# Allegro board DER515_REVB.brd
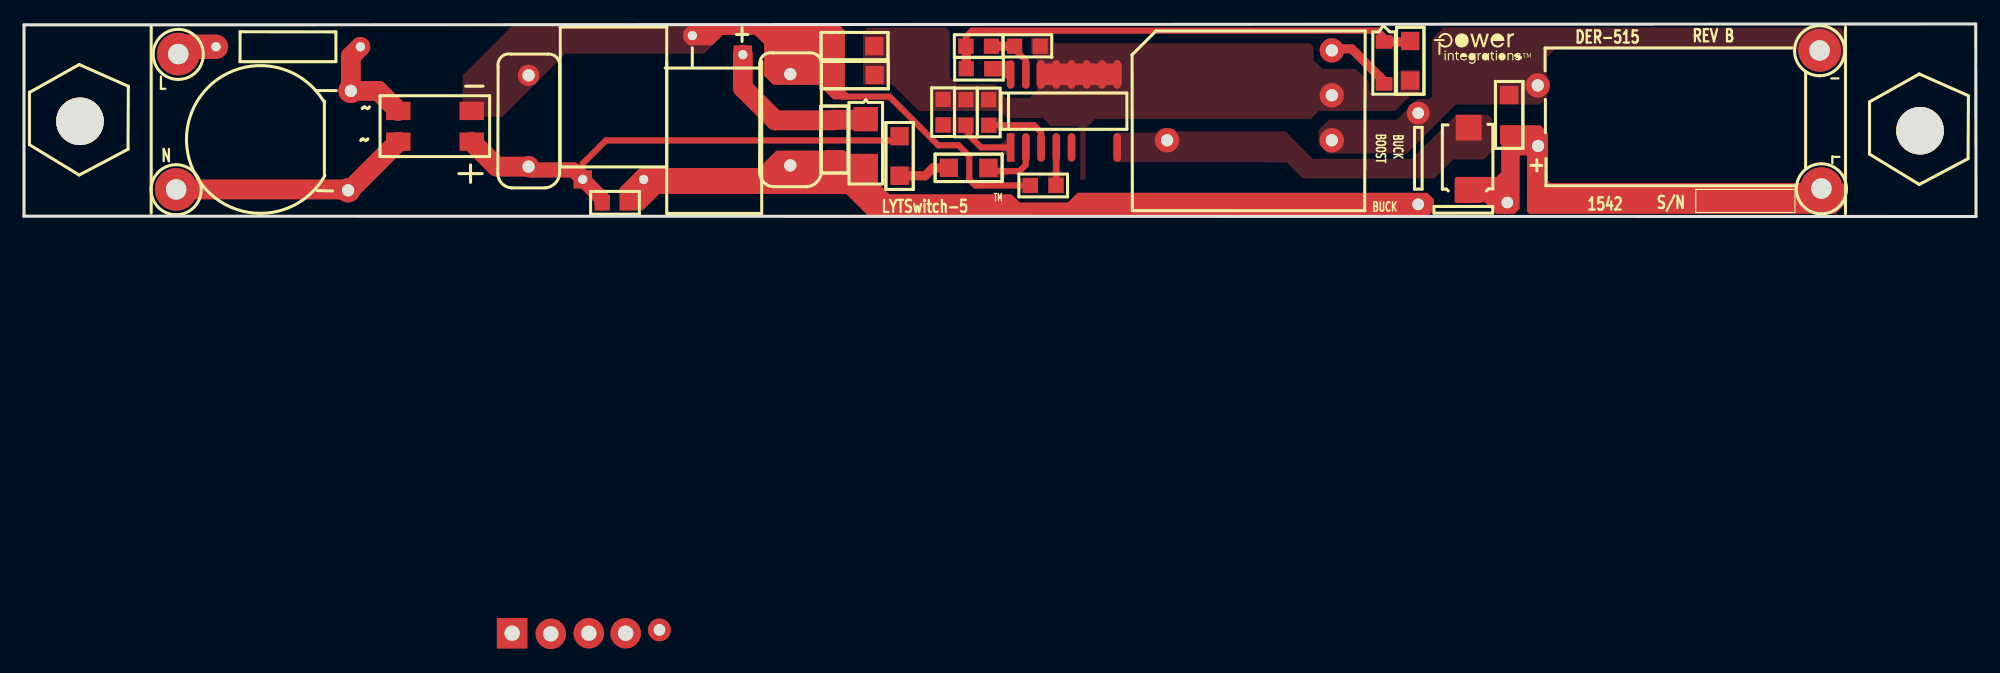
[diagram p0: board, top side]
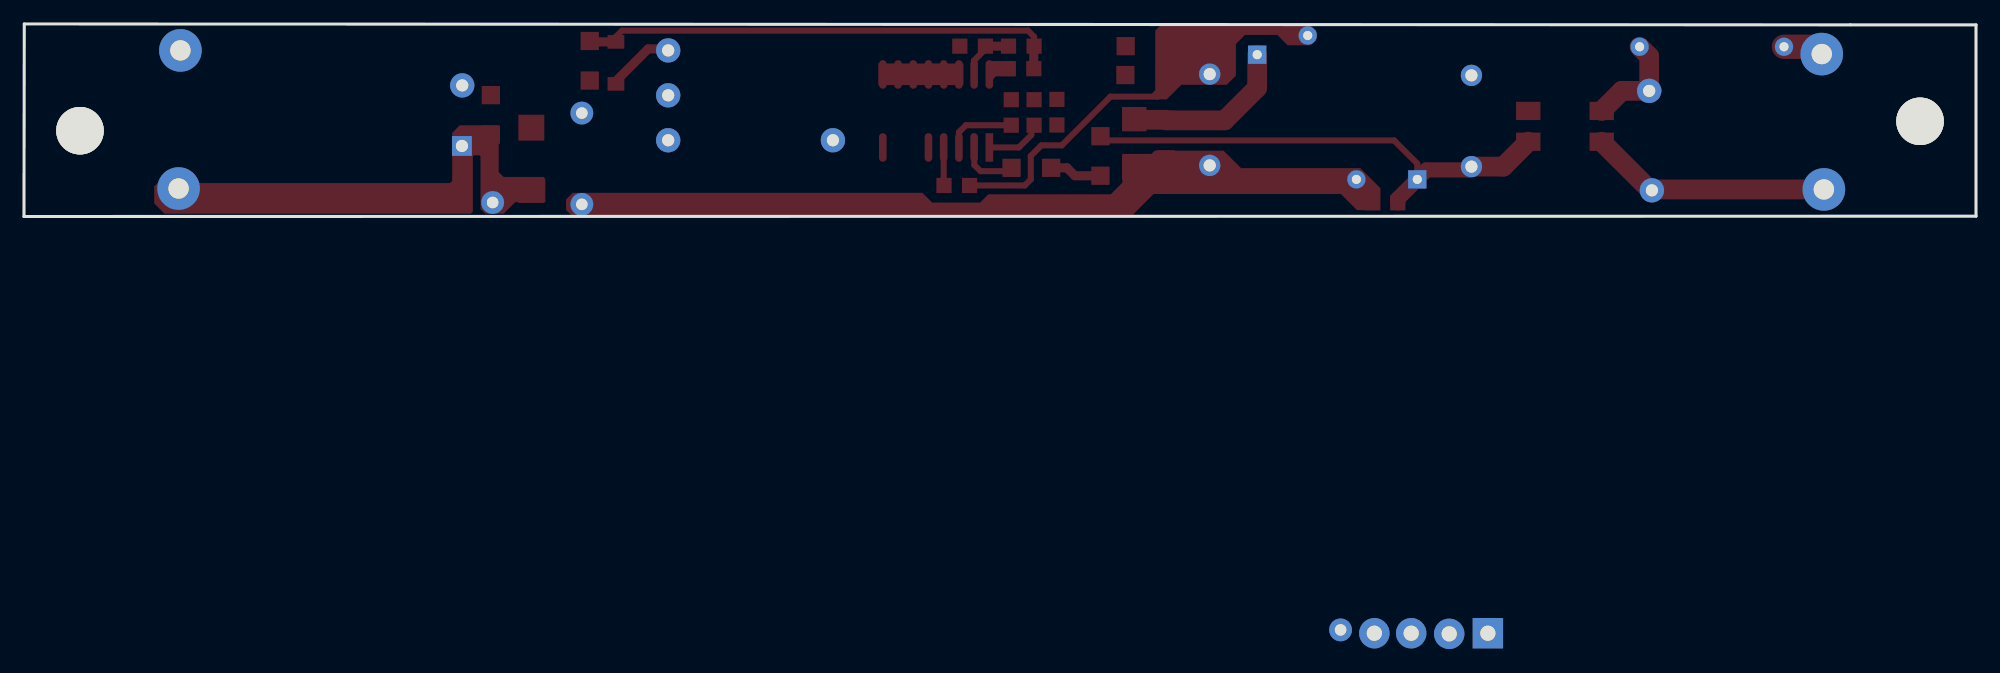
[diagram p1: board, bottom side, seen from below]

Outline 162.92 x 16.08 mm; copper layers: TOP, BOTTOM. Coordinates in mm from the lower left corner of the outline.
Outline path: 0,16 10.49,16 162.89,16.08 162.92,0 0,0.03 0,16

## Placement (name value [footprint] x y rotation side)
BR1  B10S-G  [PISMSOIC4]  31.24 8.81 270 top
C1  100 nF  [PINPCAPRAD440X200300040]  42.11 4.17 90 top
C2  100 nF  [PINPCAPRAD440X200300040]  63.96 4.27 90 top
C3  2.2 uF  [PIPOLCAPCLYD320LS140030]  57.61 15.37 180 top
C4  10uF  [PISMC1206]  67.69 11.81 0 top
C5  1 uF  [PISMC0805]  82.68 14.22 0 top
C6  150 nF  [PISMC0805]  78.61 7.62 90 top
C7  10uF  [PISMC1206]  115.7 14.66 270 top
C8  100 uF  [PIPOLCAPCYLD400LS200040]  126.42 11 270 bottom
D5  RS1K  [PISMDSMA]  70.26 8.13 270 top
D6  BAV21W-7-F  [PI_SM_SOD-123_12]  113.51 14.58 270 top
D7  MURS160T3G  [PISMSMB]  120.57 2.21 90 top
F1  5 A  [PI_V_AXIAL_160LS150D030]  22.38 14.17 180 top
JP1  J  [PI_JUMPER300]  116.36 8.64 270 top
JP2  J  [PI_JUMPER300#2]  116.18 1.17 0 top
L1  3.3 mH  [PI_CHOKE_450HX375LS197D030_H]  46.69 1.88 0 top
NOREF  -  []  0.03 0.05 0 top
NOREF#2  -  []  162.92 0 90 top
NOREF#3  -  []  117.12 15.21 0 top
NOREF#4  -  []  -158.2 54.23 0 top
NOREF#5  -  []  -236.02 -144.78 0 top
POST-CRKT_BRD_6-32_HEX1  Post Hex, 6-32, snap, 0.375L, NYL  [PIMTGHOLED156]  4.67 7.95 90 top
POST-CRKT_BRD_6-32_HEX2  Post Hex, 6-32, snap, 0.375L, NYL  [PIMTGHOLED156]  158.24 7.16 90 top
R1  10 k  [PISMR0805]  48.26 1.14 0 top
R2  680 k  [PISMR1206]  67.64 4.78 90 top
R3  2.00 M  [PISMR1206]  73.08 6.71 270 top
R4  2.00 M  [PISMR1206]  77.19 4.06 0 top
R5  100 k  [PISMR0805]  80.77 12.34 180 top
R6  6.2 k  [PISMR0805]  78.61 14.22 0 top
R7  6.04 k  [PISMR0805]  80.52 7.62 90 top
R8  6.04 k  [PISMR0805]  86.13 2.59 180 top
R9  40.2 k  [PISMR0805]  76.71 9.78 270 top
R10  3.00  [PISMR1206]  70.97 14.22 180 top
R11  82 k  [PISMR1206]  123.95 10.13 270 top
RV1  320 Vac  [PI_RAD450X550LS300D040_H]  29.18 10.54 270 bottom
T1  EFD15  [PI_BOBBIN_EFD15_8P]  95.4 13.87 0 top
TP1  BLU  [PITPKEYSTONE125X125]  12.88 13.56 0 top
TP2  WHT  [PITPKEYSTONE125X125]  12.7 2.26 0 top
TP3  RED  [PITPKEYSTONE125X125]  150.01 2.34 0 top
TP4  BLK  [PITPKEYSTONE125X125]  149.86 13.87 0 top
U1  LYT3326DG  [PI_SMD_SO_14-16P_SHORT9-14]  82.35 5.77 0 top

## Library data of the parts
BR1 = DIODE BRIDGE_~~+-: alternate symbols: (pi_sm_soic4_slot)
C1 C2 = CAP NP: alternate symbols: (pinpcaprad440x200300040h)
C3 = CAP POL: alternate symbols: (pipolcapclyd320ls140030h)
C4-C7 = CAP NP
C8 = CAP POL: alternate symbols: (pipolcapcyld400ls200040800h)
D5-D7 = DIODE
F1 = FUSE: alternate symbols: (pi_v_axial_160ls250d030,pi12wvresd180ls200d040)
JP1 JP2 = JUMPER_1
L1 = INDUCTOR: alternate symbols: (pi_choke_450hx375ls197d030_h)
POST-CRKT_BRD_6-32_HEX1 POST-CRKT_BRD_6-32_HEX2 = POST_CRKT_BRD_6-32_HEX
R1-R11 = R
RV1 = VARISTOR: alternate symbols: (pi_rad450x550ls300d040_h)
T1 = BEFD15_8P/GENERIC: alternate symbols: (pi_bobbin_efd15_8p_tape)
TP1-TP4 = TESTPOINT
U1 = LYTSW-3_SO-16

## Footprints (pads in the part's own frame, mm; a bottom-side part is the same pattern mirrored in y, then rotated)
PI_BOBBIN_EFD15_8P
  rect 2.54x2.54 hole 1.27: 1(-54.661,-48.666)
  round 2.54 hole 1.27: 2(-51.435,-48.717) 4(-48.26,-48.666) 5(-45.187,-48.666)
  round 2.032 hole 1.016: 3(0,-7.501) 6(13.749,-7.501) 7(13.749,-3.749) 8(13.749,0)
PI_CHOKE_450HX375LS197D030_H
  rect 1.524x1.524 hole 0.762: 1(-0.051,1.219)
  round 1.524 hole 0.762: 2(5.029,1.219)
PI_JUMPER300
  round 1.905 hole 0.965: 1(0,0) 2(7.62,0)
PI_JUMPER300#2
  round 1.905 hole 0.965: 1(-63.144,-35.687) 2(7.62,0)
PI_RAD450X550LS300D040_H
  round 2.032 hole 1.016: 1(0.051,1.905) 2(8.357,2.134)
PI_SM_SOD-123_12
  rect 1.143x1.397 smd: 1(0,0) 2(3.505,0)
PI_SMD_SO_14-16P_SHORT9-14
  rect 0.635x2.388 smd: 1(0,0)
  oval 0.635x2.388 smd: 2(1.27,0) 3(2.54,0) 4(3.81,0) 5(5.08,0) 8(8.89,0) 9(8.89,6.096) 10(7.62,6.096) 11(6.35,6.096) 12(5.08,6.096) 13(3.81,6.096) 14(2.54,6.096) 15(1.27,6.096) 16(0,6.096)
PI_V_AXIAL_160LS150D030
  round 1.524 hole 0.762: 1(-5.7,0) 2(6.35,0)
PIMTGHOLED156
  round 3.962 hole 3.962: 1(0,0)
PINPCAPRAD440X200300040
  round 1.778 hole 1.016: 1(0,0) 2(7.62,0)
PIPOLCAPCLYD320LS140030
  rect 1.524x1.524 hole 0.762: 1(-2.388,1.854)
  round 1.524 hole 0.762: 2(1.829,0.254)
PIPOLCAPCYLD400LS200040
  rect 1.651x1.651 hole 1.016: 1(5.105,0.051)
  round 2.032 hole 1.016: 2(0.051,0.076)
PISMC0805
  rect 1.27x1.27 smd: 1(0,0) 2(2.134,0)
PISMC1206
  rect 1.524x1.524 smd: 1(0,0) 2(3.302,0)
PISMDSMA
  rect 2.032x2.032 smd: 1(0,0) 2(4.013,0)
PISMR0805
  rect 1.27x1.27 smd: 1(0,0) 2(2.134,0)
PISMR1206
  rect 1.524x1.524 smd: 1(0,0) 2(3.302,0)
PISMSMB
  rect 2.159x2.159 smd: 1(0,0) 2(5.207,0)
PISMSOIC4
  rect 1.524x2.032 smd: 1(0,0) 2(2.571,0) 3(2.571,6.129) 4(0,6.129)
PITPKEYSTONE125X125
  round 3.556 hole 1.702: 1(0,0)

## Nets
GND: C4.2 C5.2 C6.2 C7.2 R7.2 R9.1 R10.1 T1.7 U1.9(S) U1.10(SOURCE10) U1.11(SOURCE11) U1.12(SOURCE12) U1.13(SOURCE13) U1.14(SOURCE14)
DRAIN: D7.2 T1.3 U1.8(D)
N3973903: BR1.2 RV1.2 TP2.1
N3973993: BR1.3 C1.1 L1.1 R1.1 R3.1
N3974125: BR1.4 C1.2 C2.2 C3.2 C4.1 R8.2 R10.2
N3974133: C8.1 D7.1 JP2.2 R11.2 TP3.1
N3974639: C2.1 D5.2 JP1.2 JP2.1 L1.2 R1.2 R2.1
N3976866: F1.2 TP1.1
N3988468: C5.1 R6.2 U1.15(BP)
N3988512: C6.1 R9.2 U1.1(FB)
N3988655: R8.1 U1.4(DS)
N3988764: R7.1 U1.3(BS)
N3989062: C8.2 JP1.1 R11.1 T1.6 TP4.1
N3989451: R4.2 U1.2(L)
N3989455: R3.2 R4.1
N3989712: C7.1 D6.1 R5.2 R6.1
N3989798: R5.1 U1.16(OC)
N4093345: C3.1 D5.1 R2.2
N4093437: BR1.1 F1.1 RV1.1
N4099337: D6.2 T1.8

Pads without a net: POST-CRKT_BRD_6-32_HEX1 1; POST-CRKT_BRD_6-32_HEX2 1; T1 1 2 4 5; U1 5

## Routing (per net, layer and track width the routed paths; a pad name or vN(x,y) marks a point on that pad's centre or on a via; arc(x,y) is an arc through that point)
N3973903: length 20.3
  TOP w1.651: BR1.2 27.18,2.18 RV1.2 26.97,2.26 TP2.1
N3973993: length 41.9
  TOP w0.508: 46.63,3.12 46.63,4.42 48.56,6.35 72.72,6.35 R3.1
  TOP w1.27: R1.1 48.26,1.47 L1.1 46.63,3.12 45.87,3.89 42.39,3.89 C1.1
  TOP w1.651: C1.1 39.45,4.17 BR1.3
N3974125: length 21.9
  TOP w0.508: C4.1 67.69,10.67 68.35,10.01 72.24,10.01 76.3,5.94 78,5.94 78.89,5.05 78.89,3.09 79.39,2.59 R8.2
N3976866: length 3.4
  TOP w2.032: TP1.1 13.49,14.17 F1.2
N3988468: length 4.7
  TOP w0.508: U1.15 83.62,13.03 82.68,13.97 C5.1
  TOP w0.762: R6.2 C5.1
N3988512: length 4.5
  TOP w0.508: U1.1 79.88,5.77 78.84,6.81 78.84,7.39
N3988655: length 3.2
  TOP w0.508: U1.4 86.16,2.62 R8.1
N3988764: length 5.9
  TOP w0.508: R7.1 84.3,7.62 84.89,7.04 U1.3
N3989451: length 4.9
  TOP w0.508: U1.2 83.59,4.29 83.08,3.78 80.77,3.78 R4.2
N3989455: length 4.4
  TOP w0.762: R4.1 75.87,4.06 75.21,3.4 R3.2
N3989712: length 40.6
  TOP w0.508: R6.1 78.61,15.01 79.12,15.52 113,15.52 113.51,15.01 D6.1
  TOP w0.762: C7.1 115.62,14.58 D6.1 ; R5.2 78.64,14.2 R6.1
N4093345: length 14.2
  TOP w1.27: 70.21,8.08 D5.1 ; 67.59,8.03 R2.2
  TOP w1.651: 67.59,8.03 62.71,8.03 59.99,10.74 C3.1 ; R2.2 70.21,8.08
N4093437: length 8.7
  TOP w1.651: F1.1 27.28,13.38 RV1.1 29.57,10.49 BR1.1
  TOP w2.032: 27.25,10.52 RV1.1
N4099337: length 5.8
  TOP w0.762: D6.2 113.51,11.3 110.82,14 109.28,14 T1.8

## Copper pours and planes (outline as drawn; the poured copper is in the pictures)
GND on TOP (solid shape): 91.62,10.97 84.51,10.97 84.51,12.78 91.62,12.78
GND on TOP: 84.53,10.52 84.53,13.16 84.05,13.64 84.05,14.88 84.12,14.96 85.57,14.96 86.06,14.48 107.34,14.48 107.62,14.2 107.62,13.06 108.36,12.32 111.15,12.32 112.24,11.23 112.24,10.54 112.7,10.08 114.63,10.08 114.81,10.26 114.81,12.12 114.94,12.24 116.48,12.24 116.48,10.26 115.87,10.26 114.43,8.81 108.05,8.81 107.38,8.14 89.4,8.14 88.6,7.34 88.6,3.12 88.54,3.07 88.19,3.07 88.16,3.1 88.16,7.32 87.93,7.54 85.73,7.54 85.04,8.23 82.04,8.23 81.46,8.81 74.68,8.81 72.47,11.02 70.03,11.02 70.03,15.42 70.38,15.77 76.96,15.77 77.27,15.47 77.27,11.66 77.88,11.05 81.08,11.05 81.61,10.52 81.61,10.26 81.97,9.91 83.92,9.91
DRAIN on TOP: 104.06,4.5 104.03,4.53 91.1,4.53 90.93,4.7 90.93,6.81 91.14,7.01 94.54,7.01 94.89,7.37 95.89,7.37 96.14,7.11 105.26,7.11 107.54,4.83 115.85,4.83 119.51,8.48 121.59,8.48 121.6,8.47 122.21,8.47 122.53,8.15 122.53,5.44 121.86,4.76 119.28,4.76 117.69,3.18 106.73,3.18 105.41,4.5
N3974125 on TOP (solid shape): 68.5,15.52 68.5,10.54 68.76,10.29 68.76,10.24 68.3,9.78 67.54,9.78 66.32,11 62.53,11 61.77,11.76 61.77,14.4 61.01,15.16 58.32,15.16 57.45,14.3 55.5,14.3 55.04,14.76 55.04,15.47 55.52,15.95 68.07,15.95
N3974125 on TOP: 36.6,8.33 39.93,8.33 45.19,13.59 56.74,13.59 57.45,14.3 57.45,15.7 57.2,15.95 40.77,15.95 36.6,11.79
N3974125 on TOP: 83.87,3.23 83.26,3.23 82.83,2.79 82.83,2.44 83.31,1.96 83.79,1.96 84.15,2.31 84.15,2.95
N3974133 on TOP (solid shape): 127.18,6.98 127.18,2.97 127.36,2.79 148.23,2.79 149.33,3.89 150.67,3.89 152.04,2.51 152.04,1.09 151.18,0.23 125.63,0.23 125.45,0.41 125.45,5 125.35,5.11 124.89,5.11 124.82,5.03 124.82,0.64 124.41,0.23 122.89,0.23 121.92,1.19 119.41,1.19 119.41,3.12 119.58,3.3 122.89,3.3 123.29,3.71 123.29,7.62 126.54,7.62
N3974639 on TOP (solid shape): 68.81,5.23 71.25,5.23 71.25,2.82 72.21,1.85 82.42,1.85 83.11,1.17 87.12,1.17 87.93,1.98 117.12,1.98 117.68,1.42 117.68,0.56 117.17,0.05 87.33,0.05 87.29,0.09 87.22,0.03 70.48,0.03 68.63,1.88 53.01,1.88 51.66,0.53 49.71,0.53 49.71,2.36 51.38,4.04 61.34,4.04 62.8,5.5 68.54,5.5
N3988512 on TOP: 76.07,8.31 79.2,8.31 79.27,8.23 79.27,6.38 79.25,6.35 78.92,6.35 78.28,6.98 76.1,6.98 76.05,7.04 76.05,8.28
N3988512 on TOP: 82.02,6.96 82.02,6.53 81.48,5.99 81.48,5.56 82.17,4.88 82.45,4.88 82.6,5.03 82.6,6.88 82.52,6.96
N3988655 on TOP: 86.46,5.54 86.46,3.86 86.79,3.53 86.79,2.01 86.74,1.96 85.47,1.96 85.47,3.51 85.85,3.89 85.85,5.31 86.08,5.54
N3988764 on TOP: 80.62,8.26 81.36,8.26 81.74,7.87 81.74,7.57 81.13,6.96 80.7,6.96 80.44,7.21 80.44,8.08
N3989062 on TOP: 151.94,13.36 151.05,12.47 149.35,12.47 147.83,14 127.81,14 127.13,13.31 127.13,9.96 126.52,9.35 119.51,9.35 115.42,5.26 108.84,5.26 108.05,6.05 108.05,7.21 108.92,8.08 114.58,8.08 116.31,9.8 117.3,9.8 117.5,10.01 117.5,14.83 118.45,15.79 151.57,15.79 151.94,15.42
N3989451 on TOP: 79.71,4.8 81.2,4.8 81.25,4.75 81.25,4.37 81.67,3.95 82.16,3.95 82.19,3.91 82.19,3.63 81.79,3.23 79.73,3.23 79.71,3.25
N3989455 on TOP: 72.36,4.19 73.91,4.19 74.52,3.58 74.51,3.57 74.51,3.29 73.89,2.67 72.31,2.67 72.31,4.14
N3989798 on TOP (solid shape): 82.63,12.6 82.63,11.2 82.3,11.2 81.79,11.71 80.21,11.71 80.16,11.76 80.16,12.9 80.24,12.98 82.25,12.98

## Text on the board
Ref Des/Silkscreen Top: TM | BUCK | BOOST | L | N | LYTSwitch-5 | DER-515 | 1542 | S/N | REV B | _
PEN17: CUT OUT | PLEASE DELETE THESE PINS | 13   MATERIAL FR4 COPPER 2oz THICKNESS 0.062"
User.5: FIGURE | SIZE | 30.0 | 38.0 | 40.0 | 50.0 | 67.0 | 156.0 | DRILL CHART: TOP to BOTTOM | ALL UNITS ARE IN MILS | PLATED | QTY | 6 | 4 | 12 | 2
